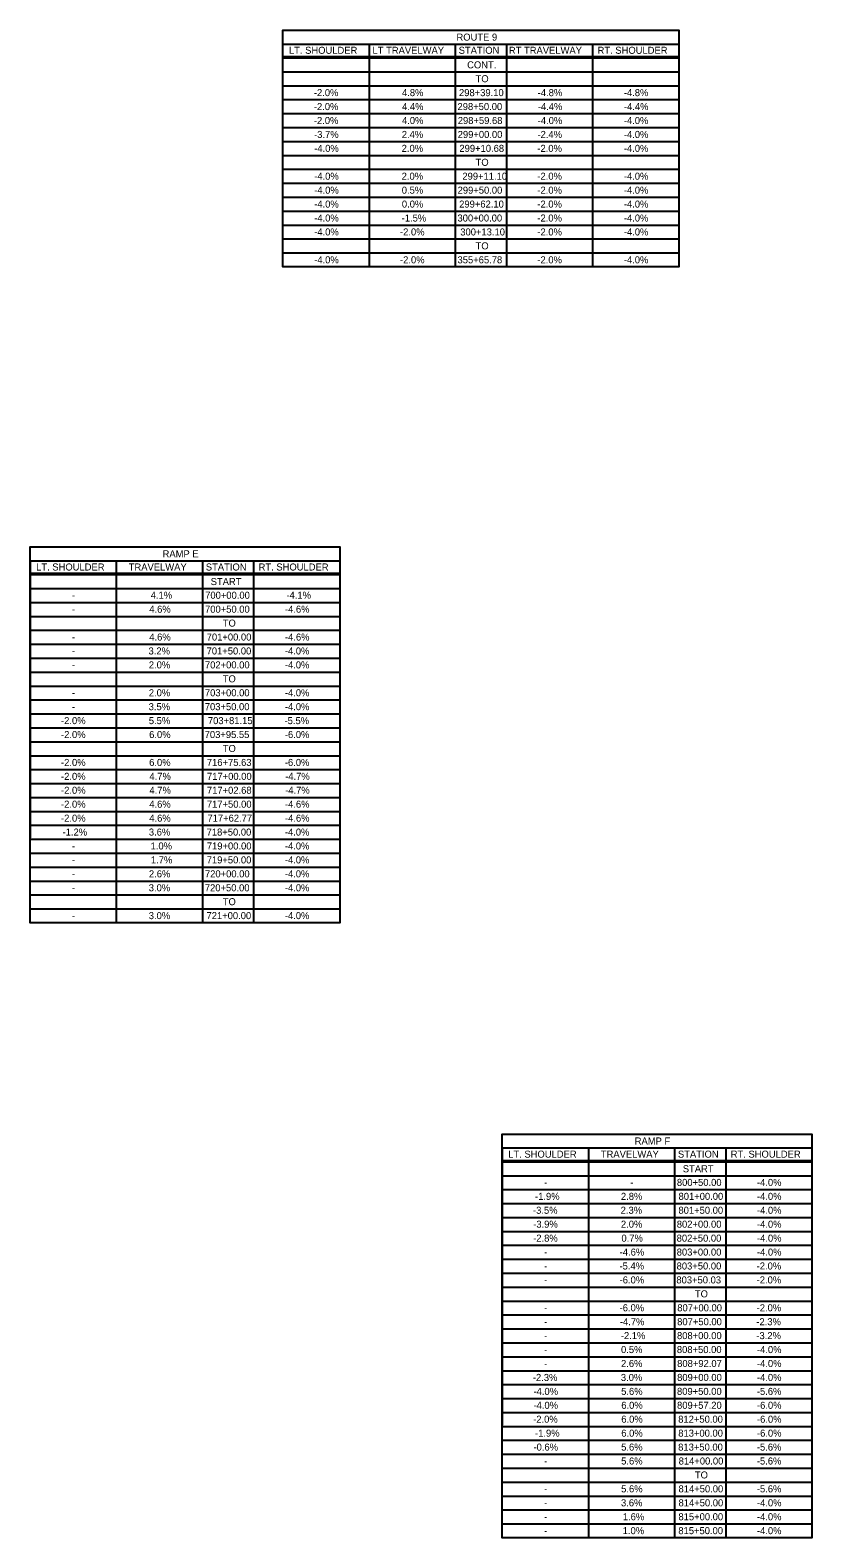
# Model space of a CAD drawing. Extents: x -15318841 to 1762012, y 465773 to 3693661.
# Drawn here: x -15316197 to -15315864, y 3691200 to 3691843 of the extents above; entities that cross this region are included whole.
import ezdxf

# ---------------------------------------------------------------- set-up
doc = ezdxf.new("R2010")
doc.units = 0
doc.layers.add('BORDER', color=7, linetype='Continuous')
doc.layers.add('DIMENSIONS', color=7, linetype='Continuous')

msp = doc.modelspace()

# ---------------------------------------------------------------- linework, layer by layer
at = {"layer": 'BORDER'}
for p, q in [((-15316052.68, 3691837.11), (-15316052.68, 3691742.1)), ((-15316015.92, 3691837.11), (-15316015.92, 3691742.1)), ((-15315994.04, 3691837.11), (-15315994.04, 3691742.1)), ((-15315957.27, 3691837.11), (-15315957.27, 3691742.1)), ((-15316089.45, 3691831.83), (-15315920.5, 3691831.83)), ((-15316089.45, 3691831.24), (-15315920.5, 3691831.24)), ((-15316089.45, 3691825.29), (-15315920.5, 3691825.29)), ((-15316089.45, 3691825.29), (-15315920.5, 3691825.29)), ((-15316089.45, 3691825.29), (-15315920.5, 3691825.29)), ((-15316089.45, 3691819.35), (-15315920.5, 3691819.35)), ((-15316089.45, 3691813.41), (-15315920.5, 3691813.41)), ((-15316089.45, 3691807.47), (-15315920.5, 3691807.47)), ((-15316089.45, 3691801.52), (-15315920.5, 3691801.52)), ((-15316089.45, 3691795.58), (-15315920.5, 3691795.58)), ((-15316089.45, 3691789.64), (-15315920.5, 3691789.64)), ((-15316089.45, 3691783.7), (-15315920.5, 3691783.7)), ((-15316089.45, 3691777.75), (-15315920.5, 3691777.75)), ((-15316089.45, 3691771.81), (-15315920.5, 3691771.81)), ((-15316089.45, 3691765.87), (-15315920.5, 3691765.87)), ((-15316089.45, 3691759.92), (-15315920.5, 3691759.92)), ((-15316089.45, 3691753.98), (-15315920.5, 3691753.98)), ((-15316089.45, 3691748.04), (-15315920.5, 3691748.04)), ((-15316197.39, 3691616.67), (-15316197.39, 3691498.47)), ((-15316160.62, 3691616.67), (-15316160.62, 3691462.23)), ((-15316123.85, 3691616.67), (-15316123.85, 3691462.23)), ((-15316101.98, 3691616.67), (-15316101.98, 3691462.23)), ((-15316197.39, 3691611.39), (-15316065.21, 3691611.39)), ((-15316197.39, 3691610.79), (-15316065.21, 3691610.79)), ((-15316197.39, 3691604.85), (-15316065.21, 3691604.85)), ((-15316197.39, 3691604.85), (-15316065.21, 3691604.85)), ((-15316197.39, 3691604.85), (-15316065.21, 3691604.85)), ((-15316197.39, 3691598.91), (-15316065.21, 3691598.91)), ((-15316197.39, 3691592.97), (-15316065.21, 3691592.97)), ((-15316197.39, 3691587.02), (-15316065.21, 3691587.02)), ((-15316197.39, 3691581.08), (-15316065.21, 3691581.08)), ((-15316197.39, 3691575.14), (-15316065.21, 3691575.14)), ((-15316197.39, 3691569.19), (-15316065.21, 3691569.19)), ((-15316197.39, 3691563.25), (-15316065.21, 3691563.25)), ((-15316197.39, 3691557.31), (-15316065.21, 3691557.31)), ((-15316197.39, 3691551.37), (-15316065.21, 3691551.37)), ((-15316197.39, 3691545.42), (-15316065.21, 3691545.42)), ((-15316197.39, 3691539.48), (-15316065.21, 3691539.48)), ((-15316197.39, 3691533.54), (-15316065.21, 3691533.54)), ((-15316197.39, 3691527.6), (-15316065.21, 3691527.6)), ((-15316197.39, 3691521.65), (-15316065.21, 3691521.65)), ((-15316197.39, 3691515.71), (-15316065.21, 3691515.71)), ((-15316197.39, 3691509.77), (-15316065.21, 3691509.77)), ((-15316197.39, 3691503.82), (-15316065.21, 3691503.82)), ((-15316197.39, 3691497.88), (-15316065.21, 3691497.88)), ((-15316197.39, 3691491.94), (-15316065.21, 3691491.94)), ((-15316197.39, 3691486), (-15316065.21, 3691486)), ((-15316197.39, 3691480.05), (-15316065.21, 3691480.05)), ((-15316197.39, 3691474.11), (-15316065.21, 3691474.11)), ((-15316197.39, 3691468.17), (-15316065.21, 3691468.17)), ((-15315995.84, 3691366.18), (-15315995.84, 3691247.98)), ((-15315959.08, 3691366.18), (-15315959.08, 3691199.85)), ((-15315922.31, 3691366.18), (-15315922.31, 3691199.85)), ((-15315900.43, 3691366.18), (-15315900.43, 3691199.85)), ((-15315995.84, 3691360.9), (-15315863.66, 3691360.9)), ((-15315995.84, 3691360.3), (-15315863.66, 3691360.3)), ((-15315995.84, 3691354.36), (-15315863.66, 3691354.36)), ((-15315995.84, 3691354.36), (-15315863.66, 3691354.36)), ((-15315995.84, 3691354.36), (-15315863.66, 3691354.36)), ((-15315995.84, 3691348.42), (-15315863.66, 3691348.42)), ((-15315995.84, 3691342.47), (-15315863.66, 3691342.47)), ((-15315995.84, 3691336.53), (-15315863.66, 3691336.53)), ((-15315995.84, 3691330.59), (-15315863.66, 3691330.59)), ((-15315995.84, 3691324.64), (-15315863.66, 3691324.64)), ((-15315995.84, 3691318.7), (-15315863.66, 3691318.7)), ((-15315995.84, 3691312.76), (-15315863.66, 3691312.76)), ((-15315995.84, 3691306.82), (-15315863.66, 3691306.82)), ((-15315995.84, 3691300.87), (-15315863.66, 3691300.87)), ((-15315995.84, 3691294.93), (-15315863.66, 3691294.93)), ((-15315995.84, 3691288.99), (-15315863.66, 3691288.99)), ((-15315995.84, 3691283.05), (-15315863.66, 3691283.05)), ((-15315995.84, 3691277.1), (-15315863.66, 3691277.1)), ((-15315995.84, 3691271.16), (-15315863.66, 3691271.16)), ((-15315995.84, 3691265.22), (-15315863.66, 3691265.22)), ((-15315995.84, 3691259.28), (-15315863.66, 3691259.28)), ((-15315995.84, 3691253.33), (-15315863.66, 3691253.33)), ((-15315995.84, 3691247.39), (-15315863.66, 3691247.39)), ((-15315995.84, 3691241.45), (-15315863.66, 3691241.45)), ((-15315995.84, 3691235.5), (-15315863.66, 3691235.5)), ((-15315995.84, 3691229.56), (-15315863.66, 3691229.56)), ((-15315995.84, 3691223.62), (-15315863.66, 3691223.62)), ((-15315995.84, 3691217.68), (-15315863.66, 3691217.68)), ((-15315995.84, 3691211.73), (-15315863.66, 3691211.73)), ((-15315995.84, 3691205.79), (-15315863.66, 3691205.79))]:
    msp.add_line(p, q, dxfattribs=at)
for points in [[(-15316089.45, 3691837.11), (-15316089.45, 3691843.06), (-15315920.5, 3691843.06), (-15315920.5, 3691837.11)], [(-15316197.39, 3691616.67), (-15316197.39, 3691622.61), (-15316065.21, 3691622.61), (-15316065.21, 3691616.67)], [(-15315995.84, 3691366.18), (-15315995.84, 3691372.12), (-15315863.66, 3691372.12), (-15315863.66, 3691366.18)]]:
    msp.add_lwpolyline(points, dxfattribs=at)
for points in [[(-15316089.45, 3691837.11), (-15315920.5, 3691837.11), (-15315920.5, 3691742.1), (-15316089.45, 3691742.1)], [(-15316197.39, 3691616.67), (-15316065.21, 3691616.67), (-15316065.21, 3691462.23), (-15316197.39, 3691462.23)], [(-15315995.84, 3691366.18), (-15315863.66, 3691366.18), (-15315863.66, 3691199.85), (-15315995.84, 3691199.85)]]:
    msp.add_lwpolyline(points, close=True, dxfattribs=at)

# ---------------------------------------------------------------- texts
at = {"layer": 'DIMENSIONS'}
for s, p in [('ROUTE 9', (-15316015.39, 3691838.59)), ('LT. SHOULDER', (-15316086.9, 3691832.97)), ('LT TRAVELWAY', (-15316051.23, 3691832.97)), ('STATION', (-15316014.45, 3691832.97)), ('RT TRAVELWAY', (-15315993.02, 3691832.97)), ('RT. SHOULDER', (-15315955.15, 3691832.97)), ('CONT.', (-15316010.82, 3691826.75)), ('TO', (-15316007.22, 3691820.84)), ('-2.0%', (-15316076.26, 3691814.9)), ('4.8%', (-15316038.64, 3691814.9)), ('298+39.10', (-15316014.3, 3691814.9)), ('-4.8%', (-15315980.71, 3691814.9)), ('-4.8%', (-15315943.94, 3691814.9)), ('-2.0%', (-15316076.26, 3691808.95)), ('4.4%', (-15316038.6, 3691808.95)), ('298+50.00', (-15316014.94, 3691808.95)), ('-4.4%', (-15315980.66, 3691808.95)), ('-4.4%', (-15315943.89, 3691808.95)), ('-2.0%', (-15316076.26, 3691803.01)), ('4.0%', (-15316038.64, 3691803.01)), ('298+59.68', (-15316014.83, 3691803.01)), ('-4.0%', (-15315980.71, 3691803.01)), ('-4.0%', (-15315943.94, 3691803.01)), ('-3.7%', (-15316076.17, 3691797.07)), ('2.4%', (-15316038.74, 3691797.07)), ('299+00.00', (-15316014.85, 3691797.07)), ('-2.4%', (-15315980.8, 3691797.07)), ('-4.0%', (-15315943.94, 3691797.07)), ('-4.0%', (-15316076.12, 3691791.13)), ('2.0%', (-15316038.78, 3691791.13)), ('299+10.68', (-15316014.13, 3691791.13)), ('TO', (-15316007.22, 3691785.18)), ('-2.0%', (-15315980.85, 3691791.13)), ('-4.0%', (-15315943.94, 3691791.13)), ('-4.0%', (-15316076.12, 3691779.24)), ('2.0%', (-15316038.78, 3691779.24)), ('299+11.10', (-15316012.86, 3691779.24)), ('-2.0%', (-15315980.85, 3691779.24)), ('-4.0%', (-15315943.94, 3691779.24)), ('-4.0%', (-15316076.12, 3691773.3)), ('0.5%', (-15316038.74, 3691773.3)), ('299+50.00', (-15316014.89, 3691773.3)), ('-2.0%', (-15315980.85, 3691773.3)), ('-4.0%', (-15315943.94, 3691773.3)), ('-4.0%', (-15316076.12, 3691767.36)), ('0.0%', (-15316038.69, 3691767.36)), ('299+62.10', (-15316014.23, 3691767.36)), ('-2.0%', (-15315980.85, 3691767.36)), ('-4.0%', (-15315943.94, 3691767.36)), ('-4.0%', (-15316076.12, 3691761.41)), ('-1.5%', (-15316038.78, 3691761.41)), ('300+00.00', (-15316014.96, 3691761.41)), ('-2.0%', (-15315980.85, 3691761.41)), ('-4.0%', (-15315943.94, 3691761.41)), ('-4.0%', (-15316076.12, 3691755.47)), ('-2.0%', (-15316039.49, 3691755.47)), ('300+13.10', (-15316013.76, 3691755.47)), ('-2.0%', (-15315980.85, 3691755.47)), ('-4.0%', (-15315943.94, 3691755.47)), ('TO', (-15316007.22, 3691749.53)), ('-4.0%', (-15316076.12, 3691743.58)), ('-2.0%', (-15316039.49, 3691743.58)), ('355+65.78', (-15316014.93, 3691743.58)), ('-2.0%', (-15315980.85, 3691743.58)), ('-4.0%', (-15315943.94, 3691743.58)), ('RAMP E', (-15316140.84, 3691618.14)), ('LT. SHOULDER', (-15316194.83, 3691612.53)), ('TRAVELWAY', (-15316155.3, 3691612.53)), ('STATION', (-15316122.39, 3691612.53)), ('RT. SHOULDER', (-15316099.85, 3691612.53)), ('START', (-15316120.31, 3691606.31)), ('-', (-15316179.51, 3691600.48)), ('4.1%', (-15316145.92, 3691600.48)), ('700+00.00', (-15316122.67, 3691600.48)), ('-4.1%', (-15316087.98, 3691600.48)), ('-', (-15316179.51, 3691594.53)), ('4.6%', (-15316146.53, 3691594.53)), ('700+50.00', (-15316122.72, 3691594.53)), ('-4.6%', (-15316088.6, 3691594.53)), ('TO', (-15316115.16, 3691588.59)), ('-', (-15316179.51, 3691582.65)), ('4.6%', (-15316146.53, 3691582.65)), ('701+00.00', (-15316122.01, 3691582.65)), ('-4.6%', (-15316088.6, 3691582.65)), ('-', (-15316179.51, 3691576.71)), ('3.2%', (-15316146.84, 3691576.71)), ('701+50.00', (-15316122.05, 3691576.71)), ('-4.0%', (-15316088.65, 3691576.71)), ('-', (-15316179.51, 3691570.76)), ('2.0%', (-15316146.72, 3691570.76)), ('702+00.00', (-15316122.76, 3691570.76)), ('-4.0%', (-15316088.65, 3691570.76)), ('TO', (-15316115.16, 3691564.82)), ('-', (-15316179.51, 3691558.88)), ('2.0%', (-15316146.72, 3691558.88)), ('703+00.00', (-15316122.79, 3691558.88)), ('-4.0%', (-15316088.65, 3691558.88)), ('-2.0%', (-15316184.2, 3691546.99)), ('-', (-15316179.51, 3691552.94)), ('3.5%', (-15316146.79, 3691552.94)), ('5.5%', (-15316146.72, 3691546.99)), ('703+50.00', (-15316122.83, 3691552.94)), ('703+81.15', (-15316121.5, 3691546.99)), ('-5.5%', (-15316088.79, 3691546.99)), ('-4.0%', (-15316088.65, 3691552.94)), ('-2.0%', (-15316184.2, 3691541.05)), ('6.0%', (-15316146.58, 3691541.05)), ('703+95.55', (-15316122.87, 3691541.05)), ('-6.0%', (-15316088.65, 3691541.05)), ('TO', (-15316115.16, 3691535.11)), ('-2.0%', (-15316184.2, 3691529.16)), ('6.0%', (-15316146.58, 3691529.16)), ('716+75.63', (-15316121.95, 3691529.16)), ('-6.0%', (-15316088.65, 3691529.16)), ('-2.0%', (-15316184.2, 3691523.22)), ('4.7%', (-15316146.46, 3691523.22)), ('717+00.00', (-15316121.89, 3691523.22)), ('-4.7%', (-15316088.53, 3691523.22)), ('-2.0%', (-15316184.2, 3691517.28)), ('4.7%', (-15316146.46, 3691517.28)), ('717+02.68', (-15316121.92, 3691517.28)), ('-4.7%', (-15316088.53, 3691517.28)), ('-2.0%', (-15316184.2, 3691511.34)), ('4.6%', (-15316146.53, 3691511.34)), ('717+50.00', (-15316121.94, 3691511.34)), ('-4.6%', (-15316088.6, 3691511.34)), ('-2.0%', (-15316184.2, 3691505.39)), ('4.6%', (-15316146.53, 3691505.39)), ('717+62.77', (-15316121.7, 3691505.39)), ('-4.6%', (-15316088.6, 3691505.39)), ('-1.2%', (-15316183.54, 3691499.45)), ('3.6%', (-15316146.7, 3691499.45)), ('718+50.00', (-15316122.05, 3691499.45)), ('-4.0%', (-15316088.65, 3691499.45)), ('-', (-15316179.51, 3691493.51)), ('1.0%', (-15316145.97, 3691493.51)), ('719+00.00', (-15316121.96, 3691493.51)), ('-4.0%', (-15316088.65, 3691493.51)), ('-', (-15316179.51, 3691487.57)), ('1.7%', (-15316145.85, 3691487.57)), ('719+50.00', (-15316122.01, 3691487.57)), ('-4.0%', (-15316088.65, 3691487.57)), ('-', (-15316179.51, 3691481.62)), ('2.6%', (-15316146.68, 3691481.62)), ('720+00.00', (-15316122.76, 3691481.62)), ('-4.0%', (-15316088.65, 3691481.62)), ('-', (-15316179.51, 3691475.68)), ('3.0%', (-15316146.75, 3691475.68)), ('720+50.00', (-15316122.81, 3691475.68)), ('TO', (-15316115.16, 3691469.74)), ('-4.0%', (-15316088.65, 3691475.68)), ('3.0%', (-15316146.75, 3691463.8)), ('721+00.00', (-15316122.1, 3691463.8)), ('-4.0%', (-15316088.65, 3691463.8)), ('-', (-15316179.51, 3691463.8)), ('RAMP F', (-15315939.29, 3691367.65)), ('LT. SHOULDER', (-15315993.29, 3691362.04)), ('TRAVELWAY', (-15315953.75, 3691362.04)), ('STATION', (-15315920.84, 3691362.04)), ('RT. SHOULDER', (-15315898.31, 3691362.04)), ('START', (-15315918.77, 3691355.81)), ('-', (-15315977.97, 3691349.99)), ('-', (-15315941.2, 3691349.99)), ('800+50.00', (-15315921.29, 3691349.99)), ('-4.0%', (-15315887.1, 3691349.99)), ('-1.9%', (-15315981.85, 3691344.04)), ('2.8%', (-15315945.18, 3691344.04)), ('801+00.00', (-15315920.58, 3691344.04)), ('-4.0%', (-15315887.1, 3691344.04)), ('-3.5%', (-15315982.72, 3691338.1)), ('2.3%', (-15315945.29, 3691338.1)), ('801+50.00', (-15315920.62, 3691338.1)), ('-4.0%', (-15315887.1, 3691338.1)), ('-3.9%', (-15315982.63, 3691332.16)), ('2.0%', (-15315945.18, 3691332.16)), ('802+00.00', (-15315921.33, 3691332.16)), ('-4.0%', (-15315887.1, 3691332.16)), ('-2.8%', (-15315982.65, 3691326.21)), ('0.7%', (-15315944.96, 3691326.21)), ('802+50.00', (-15315921.38, 3691326.21)), ('-4.0%', (-15315887.1, 3691326.21)), ('-', (-15315977.97, 3691320.27)), ('-4.6%', (-15315945.7, 3691320.27)), ('803+00.00', (-15315921.36, 3691320.27)), ('-4.0%', (-15315887.1, 3691320.27)), ('-', (-15315977.97, 3691314.33)), ('-5.4%', (-15315945.79, 3691314.33)), ('803+50.00', (-15315921.4, 3691314.33)), ('-2.0%', (-15315887.24, 3691314.33)), ('-', (-15315977.97, 3691308.39)), ('-6.0%', (-15315945.74, 3691308.39)), ('803+50.03', (-15315921.51, 3691308.39)), ('TO', (-15315913.61, 3691302.44)), ('-2.0%', (-15315887.24, 3691308.39)), ('-6.0%', (-15315945.74, 3691296.5)), ('807+00.00', (-15315921.12, 3691296.5)), ('-2.0%', (-15315887.24, 3691296.5)), ('-', (-15315977.97, 3691296.5)), ('-4.7%', (-15315945.63, 3691290.56)), ('807+50.00', (-15315921.17, 3691290.56)), ('-2.3%', (-15315887.36, 3691290.56)), ('-', (-15315977.97, 3691290.56)), ('-2.1%', (-15315945.22, 3691284.62)), ('808+00.00', (-15315921.24, 3691284.62)), ('-3.2%', (-15315887.36, 3691284.62)), ('-', (-15315977.97, 3691284.62)), ('-', (-15315977.97, 3691278.67)), ('0.5%', (-15315945.13, 3691278.67)), ('808+50.00', (-15315921.29, 3691278.67)), ('-4.0%', (-15315887.1, 3691278.67)), ('-', (-15315977.97, 3691272.73)), ('2.6%', (-15315945.13, 3691272.73)), ('808+92.07', (-15315921.17, 3691272.73)), ('-4.0%', (-15315887.1, 3691272.73)), ('-2.3%', (-15315982.77, 3691266.79)), ('3.0%', (-15315945.2, 3691266.79)), ('809+00.00', (-15315921.19, 3691266.79)), ('-4.0%', (-15315887.1, 3691266.79)), ('-4.0%', (-15315982.51, 3691260.84)), ('5.6%', (-15315945.08, 3691260.84)), ('809+50.00', (-15315921.24, 3691260.84)), ('-5.6%', (-15315887.15, 3691260.84)), ('-4.0%', (-15315982.51, 3691254.9)), ('6.0%', (-15315945.03, 3691254.9)), ('809+57.20', (-15315921.22, 3691254.9)), ('-6.0%', (-15315887.1, 3691254.9)), ('-2.0%', (-15315982.65, 3691248.96)), ('6.0%', (-15315945.03, 3691248.96)), ('812+50.00', (-15315920.72, 3691248.96)), ('-6.0%', (-15315887.1, 3691248.96)), ('-1.9%', (-15315981.85, 3691243.02)), ('6.0%', (-15315945.03, 3691243.02)), ('813+00.00', (-15315920.7, 3691243.02)), ('-6.0%', (-15315887.1, 3691243.02)), ('-0.6%', (-15315982.51, 3691237.07)), ('5.6%', (-15315945.08, 3691237.07)), ('813+50.00', (-15315920.74, 3691237.07)), ('-5.6%', (-15315887.15, 3691237.07)), ('-', (-15315977.97, 3691231.13)), ('5.6%', (-15315945.08, 3691231.13)), ('814+00.00', (-15315920.53, 3691231.13)), ('TO', (-15315913.61, 3691225.19)), ('-5.6%', (-15315887.15, 3691231.13)), ('5.6%', (-15315945.08, 3691219.25)), ('814+50.00', (-15315920.58, 3691219.25)), ('-5.6%', (-15315887.15, 3691219.25)), ('-', (-15315977.97, 3691219.25)), ('3.6%', (-15315945.15, 3691213.3)), ('814+50.00', (-15315920.58, 3691213.3)), ('-4.0%', (-15315887.1, 3691213.3)), ('-', (-15315977.97, 3691213.3)), ('1.6%', (-15315944.37, 3691207.36)), ('815+00.00', (-15315920.62, 3691207.36)), ('-4.0%', (-15315887.1, 3691207.36)), ('-', (-15315977.97, 3691207.36)), ('-', (-15315977.97, 3691201.42)), ('1.0%', (-15315944.42, 3691201.42)), ('815+50.00', (-15315920.67, 3691201.42)), ('-4.0%', (-15315887.1, 3691201.42))]:
    msp.add_text(s, height=3, dxfattribs=at).set_placement(p)

doc.saveas('drawing.dxf')
